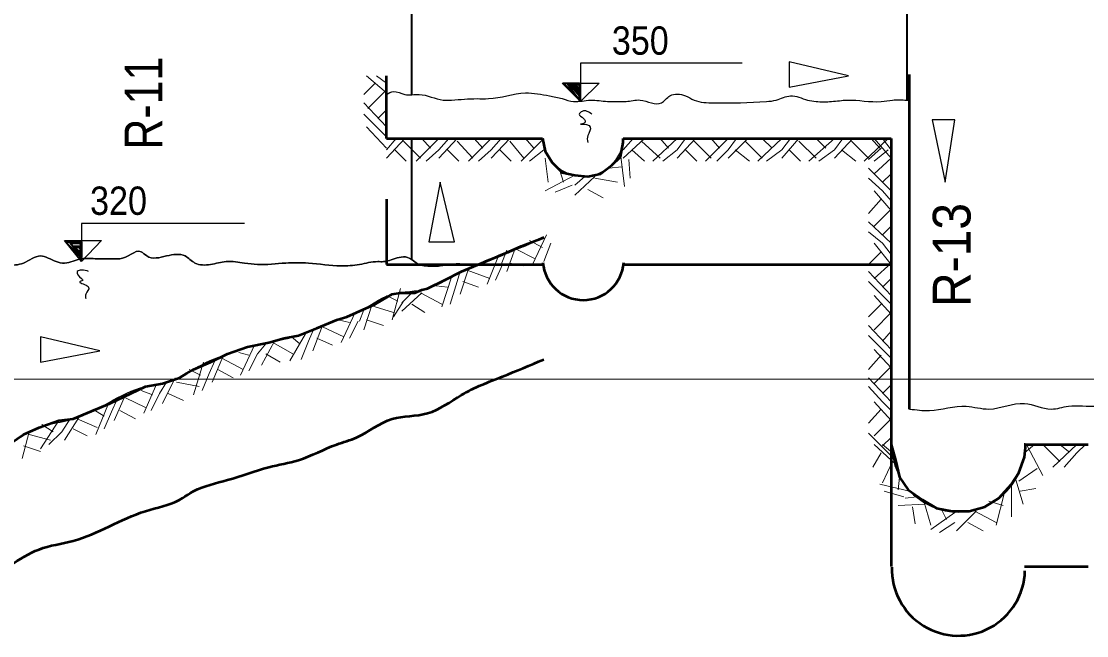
# Model space of a CAD drawing. Extents: x 8426.2 to 8495.4, y 19933.5 to 19963.2.
# Drawn here: x 8455.28 to 8462.8, y 19946.86 to 19951.2 of the extents above; entities that cross this region are included whole.
import ezdxf

# ---------------------------------------------------------------- set-up
doc = ezdxf.new("R2010")
doc.units = 0
doc.header["$LTSCALE"] = 0.11
for name, color, linetype, lineweight in [('1', 7, 'Continuous', 35), ('2', 7, 'Continuous', 13), ('3', 7, 'Continuous', 25)]:
    doc.layers.add(name, color=color, linetype=linetype, lineweight=lineweight)

msp = doc.modelspace()

# ---------------------------------------------------------------- linework, layer by layer
at = {"layer": '1'}
msp.add_line((8458.04, 19950.68), (8458.04, 19955.82), dxfattribs=at)
at = {"layer": '1', "lineweight": 25}
for points in [[(8460.37, 19950.9), (8459.23, 19950.9), (8459.23, 19950.63), (8459.1, 19950.76), (8459.36, 19950.76), (8459.23, 19950.63)], [(8456.86, 19949.77), (8455.71, 19949.77), (8455.71, 19949.5), (8455.59, 19949.65), (8455.85, 19949.65), (8455.71, 19949.5)]]:
    msp.add_lwpolyline(points, dxfattribs=at)
at = {"layer": '1'}
for points in [[(8459.23, 19950.64), (8459.11, 19950.76), (8459.22, 19950.76), (8459.22, 19950.64), (8459.14, 19950.75), (8459.22, 19950.75), (8459.22, 19950.67), (8459.16, 19950.74), (8459.2, 19950.74), (8459.22, 19950.69), (8459.18, 19950.73)], [(8459.2, 19950.7), (8459.2, 19950.73), (8459.17, 19950.73), (8459.22, 19950.69)], [(8458.04, 19949.52), (8458.04, 19949.97), (8458.04, 19950.37)], [(8455.71, 19949.52), (8455.6, 19949.64), (8455.71, 19949.64), (8455.71, 19949.53), (8455.63, 19949.63), (8455.7, 19949.63), (8455.71, 19949.54), (8455.65, 19949.61), (8455.7, 19949.61), (8455.7, 19949.57), (8455.66, 19949.6)], [(8455.7, 19949.59), (8455.69, 19949.6), (8455.65, 19949.6), (8455.7, 19949.57)]]:
    msp.add_lwpolyline(points, dxfattribs=at)
at = {"layer": '1', "lineweight": 25}
for points in [[(8459.31, 19950.54), (8459.24, 19950.56), (8459.22, 19950.54), (8459.25, 19950.51), (8459.26, 19950.48), (8459.23, 19950.47), (8459.29, 19950.46), (8459.29, 19950.41), (8459.28, 19950.39), (8459.28, 19950.34)], [(8455.76, 19949.43), (8455.71, 19949.44), (8455.68, 19949.43), (8455.71, 19949.38), (8455.72, 19949.37), (8455.7, 19949.36), (8455.75, 19949.33), (8455.76, 19949.32), (8455.74, 19949.27), (8455.74, 19949.24)]]:
    msp.add_spline(points, degree=3, dxfattribs=at)
at = {"layer": '2', "lineweight": 35}
msp.add_line((8461.53, 19955.24), (8461.53, 19950.64), dxfattribs=at)
at = {"layer": '2'}
for p, q in [((8457.86, 19950.69), (8457.72, 19950.81)), ((8457.86, 19950.76), (8457.79, 19950.81)), ((8457.78, 19950.76), (8457.7, 19950.68)), ((8457.85, 19950.7), (8457.73, 19950.58)), ((8457.86, 19950.45), (8457.7, 19950.62)), ((8457.86, 19950.57), (8457.8, 19950.51)), ((8457.79, 19950.45), (8457.7, 19950.54)), ((8457.86, 19950.3), (8457.72, 19950.45)), ((8457.86, 19950.38), (8457.79, 19950.45)), ((8457.93, 19950.37), (8457.86, 19950.29)), ((8457.99, 19950.37), (8457.86, 19950.23)), ((8457.98, 19950.35), (8458.1, 19950.23)), ((8458.23, 19950.37), (8458.07, 19950.21)), ((8458.11, 19950.37), (8458.17, 19950.3)), ((8458.3, 19950.37), (8458.23, 19950.29)), ((8458.36, 19950.37), (8458.23, 19950.23)), ((8458.36, 19950.35), (8458.47, 19950.23)), ((8458.6, 19950.37), (8458.44, 19950.21)), ((8458.48, 19950.37), (8458.54, 19950.3)), ((8458.67, 19950.37), (8458.6, 19950.29)), ((8458.73, 19950.37), (8458.6, 19950.23)), ((8458.73, 19950.35), (8458.83, 19950.23)), ((8458.97, 19950.37), (8458.81, 19950.21)), ((8458.84, 19950.37), (8458.9, 19950.3)), ((8459.6, 19950.37), (8459.53, 19950.29)), ((8459.68, 19950.37), (8459.53, 19950.23)), ((8459.66, 19950.35), (8459.79, 19950.23)), ((8459.91, 19950.37), (8459.74, 19950.21)), ((8459.79, 19950.37), (8459.85, 19950.3)), ((8459.97, 19950.37), (8459.91, 19950.29)), ((8460.04, 19950.37), (8459.91, 19950.23)), ((8460.03, 19950.35), (8460.15, 19950.23)), ((8460.27, 19950.37), (8460.11, 19950.21)), ((8460.15, 19950.37), (8460.21, 19950.3)), ((8460.33, 19950.37), (8460.27, 19950.29)), ((8460.41, 19950.37), (8460.27, 19950.23)), ((8460.39, 19950.35), (8460.51, 19950.23)), ((8460.65, 19950.37), (8460.48, 19950.21)), ((8460.51, 19950.37), (8460.58, 19950.3)), ((8460.71, 19950.37), (8460.65, 19950.29)), ((8460.77, 19950.37), (8460.65, 19950.23)), ((8460.77, 19950.35), (8460.89, 19950.23)), ((8461.02, 19950.37), (8460.84, 19950.21)), ((8460.89, 19950.37), (8460.96, 19950.3)), ((8461.08, 19950.37), (8461.02, 19950.29)), ((8461.15, 19950.37), (8461.02, 19950.23)), ((8461.14, 19950.35), (8461.26, 19950.23)), ((8461.4, 19950.37), (8461.23, 19950.21)), ((8461.28, 19950.37), (8461.34, 19950.3)), ((8461.42, 19950.23), (8461.3, 19950.37)), ((8461.42, 19950.29), (8461.36, 19950.37)), ((8457.92, 19950.29), (8458, 19950.21)), ((8458.23, 19950.29), (8458.14, 19950.21)), ((8458.29, 19950.29), (8458.37, 19950.21)), ((8458.6, 19950.29), (8458.51, 19950.21)), ((8458.66, 19950.29), (8458.74, 19950.21)), ((8458.97, 19950.29), (8458.87, 19950.21)), ((8459.51, 19950.26), (8459.54, 19950.03)), ((8459.59, 19950.29), (8459.68, 19950.21)), ((8459.91, 19950.29), (8459.81, 19950.21)), ((8459.97, 19950.29), (8460.05, 19950.21)), ((8460.27, 19950.29), (8460.19, 19950.21)), ((8460.32, 19950.29), (8460.42, 19950.21)), ((8460.65, 19950.29), (8460.54, 19950.21)), ((8460.7, 19950.29), (8460.78, 19950.21)), ((8461.02, 19950.29), (8460.91, 19950.21)), ((8461.07, 19950.29), (8461.17, 19950.21)), ((8461.35, 19950.3), (8461.26, 19950.22)), ((8461.4, 19950.29), (8461.3, 19950.21)), ((8458.98, 19950.23), (8459, 19950.06)), ((8459.43, 19950.16), (8459.52, 19950.17)), ((8459.57, 19950.22), (8459.58, 19950.09)), ((8461.42, 19950.23), (8461.3, 19950.12)), ((8459.19, 19950.11), (8458.98, 19950)), ((8459.08, 19950.15), (8459.11, 19950.06)), ((8459.26, 19950.1), (8459.19, 19950.04)), ((8459.33, 19950.1), (8459.19, 19949.97)), ((8461.42, 19950), (8461.26, 19950.16)), ((8461.42, 19950.12), (8461.36, 19950.06)), ((8459.17, 19950.04), (8459.05, 19949.99)), ((8459.33, 19950.09), (8459.49, 19950.06)), ((8461.36, 19950), (8461.26, 19950.09)), ((8459.28, 19950.01), (8459.39, 19949.95)), ((8461.42, 19949.86), (8461.3, 19950)), ((8461.42, 19949.93), (8461.36, 19950)), ((8461.35, 19949.94), (8461.26, 19949.84)), ((8461.42, 19949.87), (8461.3, 19949.75)), ((8461.42, 19949.63), (8461.26, 19949.78)), ((8461.42, 19949.75), (8461.36, 19949.69)), ((8458.87, 19949.65), (8458.96, 19949.6)), ((8458.99, 19949.69), (8458.89, 19949.48)), ((8461.36, 19949.63), (8461.26, 19949.71)), ((8458.71, 19949.58), (8458.67, 19949.48)), ((8458.77, 19949.6), (8458.71, 19949.43)), ((8458.77, 19949.59), (8458.91, 19949.52)), ((8459.02, 19949.63), (8458.97, 19949.5)), ((8461.35, 19949.57), (8461.26, 19949.48)), ((8461.42, 19949.48), (8461.3, 19949.63)), ((8461.42, 19949.55), (8461.36, 19949.63)), ((8458.65, 19949.54), (8458.57, 19949.34)), ((8458.38, 19949.43), (8458.35, 19949.33)), ((8458.44, 19949.45), (8458.38, 19949.27)), ((8458.43, 19949.44), (8458.59, 19949.38)), ((8458.54, 19949.49), (8458.62, 19949.47)), ((8458.68, 19949.48), (8458.63, 19949.37)), ((8458.73, 19949.49), (8458.83, 19949.47)), ((8461.42, 19949.26), (8461.26, 19949.43)), ((8461.42, 19949.49), (8461.3, 19949.38)), ((8458.32, 19949.39), (8458.25, 19949.18)), ((8458.4, 19949.36), (8458.51, 19949.32)), ((8461.36, 19949.26), (8461.26, 19949.36)), ((8461.42, 19949.38), (8461.36, 19949.32)), ((8457.96, 19949.31), (8457.9, 19949.09)), ((8458.04, 19949.28), (8457.97, 19949.21)), ((8458.11, 19949.28), (8457.97, 19949.15)), ((8458.1, 19949.28), (8458.25, 19949.2)), ((8458.21, 19949.33), (8458.29, 19949.32)), ((8458.35, 19949.33), (8458.31, 19949.2)), ((8457.76, 19949.2), (8457.7, 19949.02)), ((8457.86, 19949.26), (8457.94, 19949.22)), ((8457.98, 19949.22), (8457.91, 19949.11)), ((8458.04, 19949.2), (8458.13, 19949.14)), ((8461.35, 19949.2), (8461.26, 19949.11)), ((8461.42, 19949.13), (8461.3, 19949.26)), ((8461.42, 19949.2), (8461.36, 19949.26)), ((8457.64, 19949.14), (8457.54, 19948.93)), ((8457.7, 19949.16), (8457.67, 19949.08)), ((8457.75, 19949.19), (8457.91, 19949.14)), ((8461.42, 19949.14), (8461.3, 19949.02)), ((8457.41, 19949.05), (8457.34, 19948.87)), ((8457.52, 19949.09), (8457.6, 19949.07)), ((8457.66, 19949.08), (8457.6, 19948.96)), ((8457.72, 19949.09), (8457.84, 19949.05)), ((8461.42, 19948.88), (8461.26, 19949.05)), ((8457.29, 19948.99), (8457.18, 19948.8)), ((8457.19, 19948.97), (8457.25, 19948.92)), ((8457.35, 19949.03), (8457.31, 19948.94)), ((8457.41, 19949.04), (8457.56, 19948.97)), ((8461.36, 19948.88), (8461.26, 19948.98)), ((8461.42, 19949.01), (8461.36, 19948.94)), ((8456.93, 19948.91), (8456.83, 19948.7)), ((8457.01, 19948.92), (8456.95, 19948.85)), ((8457.07, 19948.94), (8456.98, 19948.77)), ((8457.06, 19948.93), (8457.2, 19948.85)), ((8457.31, 19948.94), (8457.26, 19948.81)), ((8457.37, 19948.96), (8457.48, 19948.91)), ((8456.71, 19948.84), (8456.63, 19948.65)), ((8456.7, 19948.82), (8456.85, 19948.74)), ((8456.82, 19948.86), (8456.89, 19948.84)), ((8456.95, 19948.85), (8456.89, 19948.73)), ((8457.01, 19948.85), (8457.11, 19948.79)), ((8461.35, 19948.84), (8461.26, 19948.74)), ((8461.42, 19948.75), (8461.3, 19948.88)), ((8461.42, 19948.82), (8461.36, 19948.88)), ((8456.57, 19948.79), (8456.5, 19948.56)), ((8456.65, 19948.8), (8456.61, 19948.71)), ((8461.42, 19948.76), (8461.3, 19948.64)), ((8456.37, 19948.68), (8456.28, 19948.5)), ((8456.47, 19948.74), (8456.55, 19948.7)), ((8456.61, 19948.71), (8456.56, 19948.59)), ((8456.67, 19948.74), (8456.78, 19948.68)), ((8461.42, 19948.51), (8461.26, 19948.68)), ((8456.24, 19948.64), (8456.15, 19948.43)), ((8456.31, 19948.65), (8456.26, 19948.57)), ((8456.38, 19948.65), (8456.54, 19948.62)), ((8461.36, 19948.51), (8461.26, 19948.62)), ((8461.42, 19948.63), (8461.36, 19948.57)), ((8455.96, 19948.53), (8455.92, 19948.44)), ((8456.02, 19948.56), (8455.94, 19948.38)), ((8456.02, 19948.54), (8456.16, 19948.47)), ((8456.13, 19948.59), (8456.21, 19948.56)), ((8456.26, 19948.57), (8456.2, 19948.45)), ((8456.32, 19948.57), (8456.43, 19948.52)), ((8455.79, 19948.46), (8455.87, 19948.41)), ((8455.9, 19948.5), (8455.81, 19948.28)), ((8455.92, 19948.44), (8455.87, 19948.32)), ((8455.98, 19948.45), (8456.09, 19948.39)), ((8461.35, 19948.46), (8461.26, 19948.36)), ((8461.42, 19948.38), (8461.3, 19948.51)), ((8461.42, 19948.45), (8461.36, 19948.51)), ((8455.55, 19948.38), (8455.42, 19948.18)), ((8455.63, 19948.39), (8455.57, 19948.3)), ((8455.69, 19948.4), (8455.59, 19948.24)), ((8455.68, 19948.39), (8455.82, 19948.33)), ((8461.42, 19948.39), (8461.3, 19948.27)), ((8455.34, 19948.3), (8455.29, 19948.11)), ((8455.43, 19948.35), (8455.51, 19948.3)), ((8455.57, 19948.3), (8455.48, 19948.21)), ((8455.65, 19948.32), (8455.75, 19948.27)), ((8461.42, 19948.13), (8461.26, 19948.29)), ((8455.34, 19948.28), (8455.49, 19948.24)), ((8461.42, 19948.26), (8461.36, 19948.2)), ((8455.3, 19948.2), (8455.42, 19948.16)), ((8461.35, 19948.15), (8461.29, 19948.05)), ((8461.45, 19948.07), (8461.3, 19948.21)), ((8461.43, 19948.15), (8461.36, 19948.21)), ((8462.43, 19948.21), (8462.36, 19948.15)), ((8462.38, 19948.2), (8462.49, 19947.99)), ((8462.49, 19948.21), (8462.61, 19948.09)), ((8462.73, 19948.21), (8462.56, 19948.05)), ((8462.61, 19948.21), (8462.67, 19948.16)), ((8462.73, 19948.15), (8462.64, 19948.05)), ((8462.79, 19948.21), (8462.73, 19948.15)), ((8461.43, 19948.09), (8461.36, 19947.94)), ((8462.32, 19947.95), (8462.45, 19948.04)), ((8461.55, 19947.88), (8461.34, 19947.93)), ((8461.48, 19947.98), (8461.47, 19947.89)), ((8462.27, 19947.93), (8462.27, 19947.82)), ((8462.3, 19947.96), (8462.35, 19947.79)), ((8461.51, 19947.84), (8461.37, 19947.88)), ((8461.6, 19947.84), (8461.52, 19947.83)), ((8462.22, 19947.87), (8462.16, 19947.64)), ((8462.33, 19947.88), (8462.44, 19947.9)), ((8461.66, 19947.79), (8461.47, 19947.78)), ((8461.57, 19947.77), (8461.59, 19947.65)), ((8461.65, 19947.81), (8461.7, 19947.64)), ((8462.11, 19947.81), (8462.21, 19947.78)), ((8462.27, 19947.82), (8462.27, 19947.7)), ((8461.87, 19947.73), (8461.7, 19947.61)), ((8461.77, 19947.76), (8461.81, 19947.68)), ((8462.02, 19947.74), (8461.88, 19947.6)), ((8462.01, 19947.74), (8462.16, 19947.66)), ((8461.87, 19947.66), (8461.76, 19947.59)), ((8461.96, 19947.66), (8462.07, 19947.6))]:
    msp.add_line(p, q, dxfattribs=at)
at = {"layer": '2', "lineweight": 53}
for p, q in [((8457.86, 19950.37), (8457.86, 19950.81)), ((8461.55, 19948.46), (8461.55, 19950.82)), ((8461.55, 19948.46), (8461.55, 19950.82)), ((8457.86, 19950.37), (8458.96, 19950.37)), ((8459.53, 19950.37), (8461.42, 19950.37)), ((8461.42, 19950.37), (8461.42, 19948.21)), ((8457.86, 19949.94), (8457.86, 19949.48)), ((8457.86, 19949.48), (8458.96, 19949.48)), ((8459.53, 19949.48), (8461.42, 19949.48)), ((8461.42, 19949.48), (8461.42, 19947.35)), ((8462.36, 19948.21), (8462.81, 19948.21)), ((8462.36, 19947.35), (8462.81, 19947.35))]:
    msp.add_line(p, q, dxfattribs=at)
at = {"layer": '2', "lineweight": 25}
msp.add_line((8457.86, 19950.81), (8457.86, 19950.37), dxfattribs=at)
for points in [[(8461.12, 19950.81), (8460.7, 19950.91), (8460.7, 19950.73)], [(8461.8, 19950.06), (8461.87, 19950.5), (8461.71, 19950.5)], [(8458.24, 19950.06), (8458.16, 19949.64), (8458.34, 19949.64)], [(8455.84, 19948.87), (8455.42, 19948.97), (8455.42, 19948.79)]]:
    msp.add_lwpolyline(points, close=True, dxfattribs=at)
at = {"layer": '2', "lineweight": 53}
for points in [[(8458.96, 19950.37), (8458.98, 19950.28), (8459.03, 19950.2), (8459.1, 19950.13), (8459.19, 19950.11), (8459.28, 19950.1), (8459.37, 19950.12), (8459.45, 19950.18), (8459.51, 19950.24), (8459.53, 19950.34), (8459.53, 19950.37)], [(8455.21, 19948.22), (8455.3, 19948.28), (8455.41, 19948.33), (8455.47, 19948.35), (8455.55, 19948.38), (8455.65, 19948.39), (8455.91, 19948.5), (8456.16, 19948.62), (8456.28, 19948.64), (8456.4, 19948.68), (8456.45, 19948.71), (8456.5, 19948.74), (8456.62, 19948.79), (8456.74, 19948.85), (8456.88, 19948.9), (8457.03, 19948.93), (8457.14, 19948.96), (8457.24, 19948.98), (8457.37, 19949.03), (8457.51, 19949.09), (8457.58, 19949.11), (8457.65, 19949.14), (8457.78, 19949.2), (8457.9, 19949.27), (8457.96, 19949.28), (8458.06, 19949.28), (8458.11, 19949.3), (8458.15, 19949.31), (8458.27, 19949.37), (8458.39, 19949.43), (8458.53, 19949.49), (8458.68, 19949.55), (8458.81, 19949.61), (8458.97, 19949.67)], [(8461.42, 19948.21), (8461.45, 19948.1), (8461.48, 19947.98), (8461.54, 19947.89), (8461.64, 19947.82), (8461.74, 19947.76), (8461.85, 19947.74), (8461.97, 19947.74), (8462.08, 19947.77), (8462.18, 19947.83), (8462.27, 19947.93), (8462.32, 19948.01), (8462.36, 19948.12), (8462.37, 19948.21)]]:
    msp.add_lwpolyline(points, dxfattribs=at)
for centre, radius, start, end in [((8459.2489, 19949.5144), 0.2856, 184.04861, 355.95139), ((8461.8944, 19947.3303), 0.4695, 178.14976, 358.67699)]:
    msp.add_arc(centre, radius, start, end, dxfattribs=at)
for points in [[(8458.97, 19949.67), (8458.68, 19949.55), (8458.44, 19949.45)], [(8454.87, 19947.21), (8454.94, 19947.24), (8455.12, 19947.31), (8455.21, 19947.36), (8455.41, 19947.47), (8455.65, 19947.53), (8456.16, 19947.74), (8456.4, 19947.82), (8456.5, 19947.88), (8456.74, 19947.96), (8457.03, 19948.05), (8457.24, 19948.1), (8457.51, 19948.21), (8457.65, 19948.26), (8457.9, 19948.39), (8458.15, 19948.43), (8458.39, 19948.56), (8458.68, 19948.69), (8458.97, 19948.81)]]:
    msp.add_spline(points, degree=3, dxfattribs=at)
at = {"layer": '3', "lineweight": 13}
msp.add_line((8431.27, 19948.67), (8493.73, 19948.67), dxfattribs=at)
at = {"layer": '3'}
msp.add_line((8462.81, 19948.21), (8462.37, 19948.21), dxfattribs=at)
for points in [[(8458.96, 19950.37), (8457.86, 19950.37), (8457.86, 19950.68)], [(8461.42, 19948.21), (8461.42, 19950.37), (8459.53, 19950.37)]]:
    msp.add_lwpolyline(points, dxfattribs=at)
for centre, radius, start, end in [((8459.2489, 19950.387), 0.2856, 184.04861, 355.95139), ((8461.8944, 19948.203), 0.4695, 178.14976, 1.84193)]:
    msp.add_arc(centre, radius, start, end, dxfattribs=at)
for points in [[(8457.86, 19950.68), (8457.91, 19950.7), (8457.99, 19950.68), (8458.09, 19950.68), (8458.26, 19950.64), (8458.32, 19950.64), (8458.5, 19950.65), (8458.58, 19950.65), (8458.84, 19950.69), (8459.01, 19950.67), (8459.1, 19950.65), (8459.18, 19950.63), (8459.3, 19950.64), (8459.42, 19950.63), (8459.51, 19950.63), (8459.55, 19950.63), (8459.65, 19950.64), (8459.8, 19950.62), (8459.86, 19950.67), (8459.97, 19950.67), (8460.03, 19950.64), (8460.17, 19950.62), (8460.54, 19950.63), (8460.61, 19950.64), (8460.71, 19950.67), (8460.83, 19950.64), (8460.89, 19950.63), (8461, 19950.63), (8461.11, 19950.64), (8461.35, 19950.63), (8461.43, 19950.64), (8461.53, 19950.64), (8461.55, 19950.64)], [(8457.86, 19950.68), (8457.91, 19950.7), (8457.99, 19950.68), (8458.09, 19950.68), (8458.26, 19950.64), (8458.32, 19950.64), (8458.5, 19950.65), (8458.58, 19950.65), (8458.84, 19950.69), (8459.01, 19950.67), (8459.1, 19950.65), (8459.18, 19950.63), (8459.3, 19950.64), (8459.42, 19950.63), (8459.51, 19950.63), (8459.55, 19950.63), (8459.65, 19950.64), (8459.8, 19950.62), (8459.86, 19950.67), (8459.97, 19950.67), (8460.03, 19950.64), (8460.17, 19950.62), (8460.54, 19950.63), (8460.61, 19950.64), (8460.71, 19950.67), (8460.83, 19950.64), (8460.89, 19950.63), (8461, 19950.63), (8461.11, 19950.64), (8461.35, 19950.63), (8461.43, 19950.64), (8461.53, 19950.64), (8461.55, 19950.64)], [(8454.79, 19949.52), (8454.95, 19949.54), (8455.08, 19949.52), (8455.19, 19949.48), (8455.3, 19949.49), (8455.42, 19949.54), (8455.53, 19949.5), (8455.59, 19949.49), (8455.71, 19949.52), (8455.82, 19949.52), (8455.97, 19949.52), (8455.98, 19949.52), (8456.13, 19949.57), (8456.17, 19949.54), (8456.31, 19949.54), (8456.44, 19949.54), (8456.51, 19949.49), (8456.62, 19949.48), (8456.73, 19949.5), (8456.86, 19949.49), (8456.95, 19949.48), (8457.15, 19949.49), (8457.31, 19949.49), (8457.54, 19949.47), (8457.67, 19949.48), (8457.8, 19949.5), (8457.84, 19949.5), (8457.95, 19949.53), (8458.01, 19949.53), (8458.09, 19949.48), (8458.14, 19949.47), (8458.24, 19949.47), (8458.31, 19949.48), (8458.42, 19949.48), (8458.47, 19949.47)], [(8458.47, 19949.47), (8458.42, 19949.48), (8458.31, 19949.48), (8458.24, 19949.47), (8458.14, 19949.47), (8458.09, 19949.48), (8458.01, 19949.53), (8457.95, 19949.53), (8457.84, 19949.5), (8457.8, 19949.5), (8457.67, 19949.48), (8457.54, 19949.47), (8457.31, 19949.49), (8457.15, 19949.49), (8456.95, 19949.48), (8456.86, 19949.49), (8456.73, 19949.5), (8456.62, 19949.48), (8456.51, 19949.49), (8456.44, 19949.54), (8456.31, 19949.54), (8456.17, 19949.54), (8456.13, 19949.57), (8455.98, 19949.52), (8455.97, 19949.52), (8455.82, 19949.52), (8455.71, 19949.52), (8455.59, 19949.49), (8455.53, 19949.5), (8455.42, 19949.54), (8455.3, 19949.49), (8455.19, 19949.48), (8455.08, 19949.52), (8454.95, 19949.54), (8454.79, 19949.52)], [(8454.87, 19948.09), (8454.94, 19948.1), (8455.12, 19948.17), (8455.21, 19948.22), (8455.41, 19948.33), (8455.65, 19948.39), (8456.16, 19948.62), (8456.4, 19948.68), (8456.5, 19948.74), (8456.74, 19948.85), (8457.03, 19948.93), (8457.24, 19948.98), (8457.51, 19949.09), (8457.65, 19949.14), (8457.9, 19949.27), (8458.15, 19949.31), (8458.39, 19949.43), (8458.44, 19949.45)], [(8461.55, 19948.46), (8461.69, 19948.45), (8461.95, 19948.48), (8462.11, 19948.46), (8462.36, 19948.5), (8462.55, 19948.46), (8462.67, 19948.48), (8462.87, 19948.48), (8463.01, 19948.5), (8463.36, 19948.5), (8463.52, 19948.51), (8463.65, 19948.51), (8463.76, 19948.51), (8463.97, 19948.47), (8464.06, 19948.5), (8464.31, 19948.48), (8464.45, 19948.5), (8464.65, 19948.47), (8464.77, 19948.47), (8464.91, 19948.48), (8465.03, 19948.45), (8465.17, 19948.46), (8465.41, 19948.45), (8465.58, 19948.47), (8465.71, 19948.43), (8465.82, 19948.45), (8465.98, 19948.45), (8466.11, 19948.47), (8466.22, 19948.41), (8466.29, 19948.45), (8466.42, 19948.44), (8466.48, 19948.41), (8466.59, 19948.45), (8466.65, 19948.45), (8466.67, 19948.43), (8466.81, 19948.45)], [(8461.55, 19948.46), (8461.69, 19948.45), (8461.95, 19948.48), (8462.11, 19948.46), (8462.36, 19948.5), (8462.55, 19948.46), (8462.67, 19948.48), (8462.87, 19948.48), (8463.01, 19948.5), (8463.36, 19948.5), (8463.52, 19948.51), (8463.65, 19948.51), (8463.76, 19948.51), (8463.97, 19948.47), (8464.06, 19948.5), (8464.31, 19948.48), (8464.45, 19948.5), (8464.65, 19948.47), (8464.77, 19948.47), (8464.91, 19948.48), (8465.03, 19948.45), (8465.17, 19948.46), (8465.41, 19948.45), (8465.58, 19948.47), (8465.71, 19948.43), (8465.82, 19948.45), (8465.98, 19948.45), (8466.11, 19948.47), (8466.22, 19948.41), (8466.29, 19948.45), (8466.42, 19948.44), (8466.48, 19948.41), (8466.59, 19948.45), (8466.65, 19948.45), (8466.67, 19948.43), (8466.81, 19948.45)]]:
    msp.add_spline(points, degree=3, dxfattribs=at)

# ---------------------------------------------------------------- texts
at = {"layer": '1'}
for s, width, p in [('R-11', 0.85, (8456.28, 19950.29)), ('R-13', 0.95, (8461.98, 19949.18))]:
    msp.add_text(s, height=0.2665, rotation=90, dxfattribs=dict(at, width=width)).set_placement(p)
at = {"layer": '2', "width": 0.9}
for s, p in [('350', (8459.45, 19950.96)), ('320', (8455.77, 19949.83))]:
    msp.add_text(s, height=0.1999, dxfattribs=at).set_placement(p)

doc.saveas('drawing.dxf')
